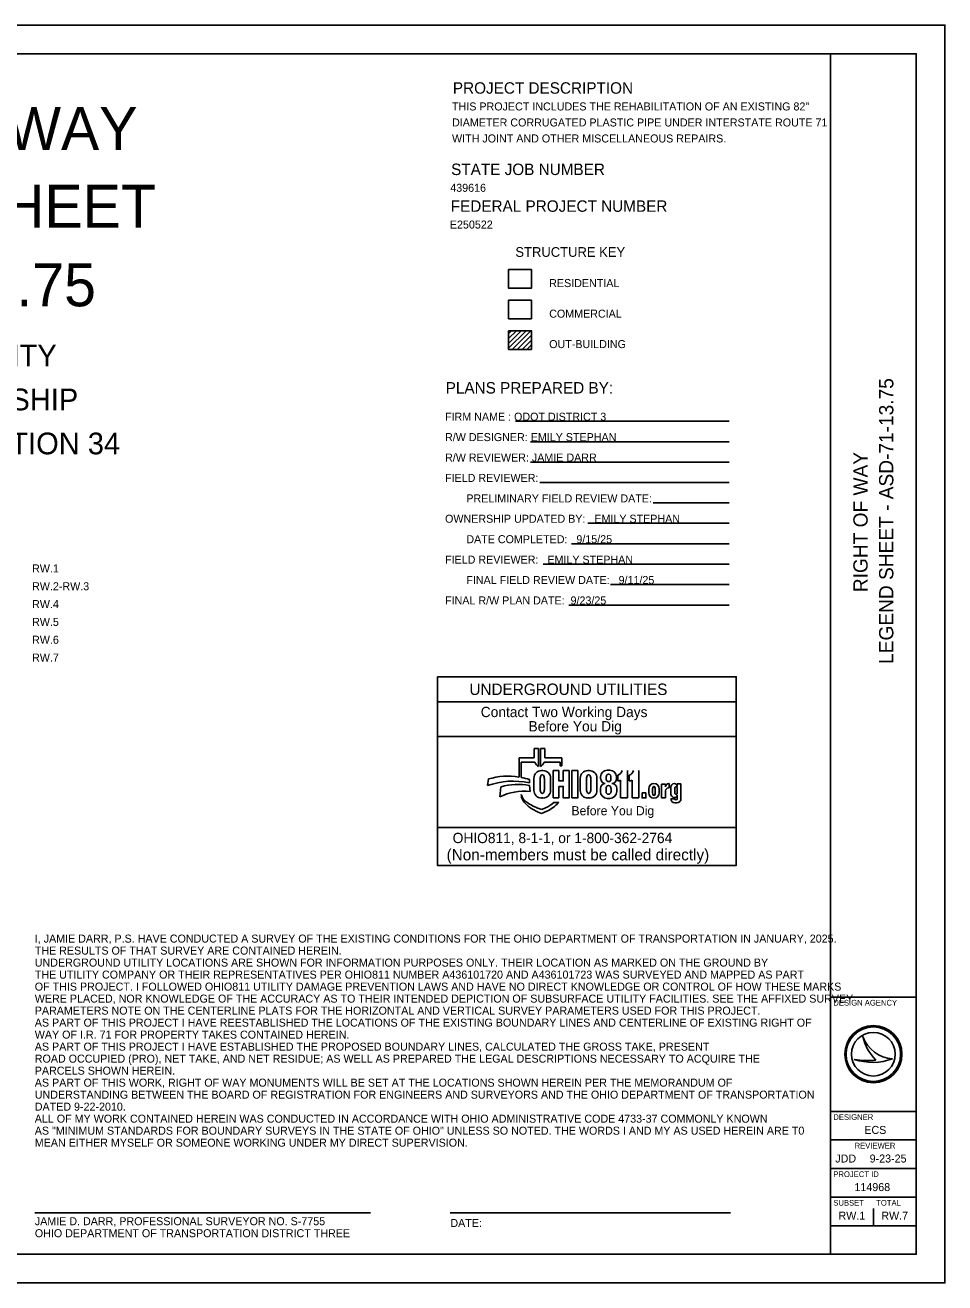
# Model space of a CAD drawing. Extents: x 0 to 34, y 0 to 22.
# Drawn here: x 17.92 to 34, y 0 to 22 of the extents above; entities that cross this region are included whole.
import ezdxf

# ---------------------------------------------------------------- set-up
doc = ezdxf.new("R2010")
doc.units = 0
for name, color, linetype in [('SC_Shading1', 7, 'Continuous'), ('SH_Border', 7, 'Continuous'), ('SH_Cut_Line', 7, 'Continuous'), ('SH_Data', 7, 'Continuous'), ('SH_Text', 7, 'Continuous')]:
    doc.layers.add(name, color=color, linetype=linetype)

msp = doc.modelspace()

# ---------------------------------------------------------------- linework, layer by layer
at = {"layer": 'SC_Shading1'}
msp.add_lwpolyline([(26.372, 16.863), (26.769, 16.863), (26.769, 17.188), (26.372, 17.188)], close=True, dxfattribs=at)
at = {"layer": 'SH_Border'}
for p, q in [((32, 0.5), (32, 21.5)), ((32, 5), (33.5, 5)), ((32, 3), (33.5, 3)), ((32, 2.5), (33.5, 2.5)), ((32, 2), (33.5, 2)), ((32, 1.5), (33.5, 1.5)), ((32, 1), (33.5, 1))]:
    msp.add_line(p, q, dxfattribs=at)
msp.add_lwpolyline([(1.5, 21.5), (33.5, 21.5), (33.5, 0.5), (1.5, 0.5)], close=True, dxfattribs=at)
at = {"layer": 'SH_Cut_Line'}
msp.add_lwpolyline([(0, 0), (34, 0), (34, 22), (0, 22)], close=True, dxfattribs=at)
at = {"layer": 'SH_Data'}
for p, q in [((26.896, 9.349), (26.816, 9.349)), ((26.816, 9.349), (26.816, 9.182)), ((26.896, 9.032), (26.896, 9.349)), ((27.007, 9.349), (26.927, 9.349)), ((26.927, 9.349), (26.927, 9.032)), ((27.007, 9.182), (27.007, 9.349)), ((26.816, 9.182), (26.553, 9.182)), ((26.553, 9.182), (26.553, 8.848)), ((26.59, 8.841), (26.59, 9.105)), ((26.59, 9.105), (26.831, 9.105)), ((26.991, 9.105), (27.27, 9.105)), ((27.304, 9.182), (27.007, 9.182)), ((27.27, 9.105), (27.27, 9.042)), ((27.27, 9.042), (27.304, 9.042)), ((27.304, 9.042), (27.304, 9.182)), ((26.018, 8.814), (26.004, 8.697)), ((26.737, 8.746), (26.737, 8.804)), ((26.814, 8.827), (26.814, 8.615)), ((26.923, 8.632), (26.923, 8.815)), ((26.972, 8.961), (26.948, 8.961)), ((26.997, 8.815), (26.997, 8.632)), ((27.106, 8.615), (27.106, 8.827)), ((27.25, 8.96), (27.149, 8.96)), ((27.149, 8.96), (27.149, 8.482)), ((27.625, 8.827), (27.625, 8.615)), ((27.734, 8.632), (27.734, 8.815)), ((27.783, 8.961), (27.758, 8.961)), ((27.808, 8.815), (27.808, 8.632)), ((27.917, 8.615), (27.917, 8.827)), ((27.981, 8.854), (27.981, 8.817)), ((28.08, 8.8), (28.08, 8.859)), ((28.144, 8.968), (28.095, 8.968)), ((28.161, 8.859), (28.161, 8.8)), ((28.258, 8.817), (28.258, 8.854)), ((28.281, 8.779), (28.281, 8.881)), ((28.448, 8.96), (28.448, 8.482)), ((28.481, 8.779), (28.481, 8.881)), ((28.648, 8.96), (28.648, 8.482)), ((26.238, 8.678), (26.216, 8.499)), ((26.747, 8.595), (26.737, 8.701)), ((27.25, 8.482), (27.25, 8.684)), ((27.976, 8.647), (27.976, 8.596)), ((28.077, 8.587), (28.077, 8.649)), ((28.162, 8.649), (28.162, 8.587)), ((28.264, 8.596), (28.264, 8.647)), ((28.329, 8.482), (28.329, 8.793)), ((28.53, 8.482), (28.53, 8.793)), ((28.822, 8.573), (28.822, 8.64)), ((28.889, 8.571), (28.889, 8.64)), ((28.937, 8.64), (28.937, 8.571)), ((29.004, 8.64), (29.004, 8.573)), ((29.117, 8.725), (29.044, 8.725)), ((29.044, 8.725), (29.044, 8.482)), ((29.117, 8.678), (29.117, 8.725)), ((29.117, 8.482), (29.117, 8.609)), ((29.166, 8.658), (29.178, 8.658)), ((29.178, 8.733), (29.172, 8.733)), ((29.178, 8.658), (29.178, 8.733)), ((29.206, 8.56), (29.206, 8.664)), ((29.278, 8.574), (29.278, 8.65)), ((29.321, 8.68), (29.321, 8.726)), ((29.321, 8.726), (29.386, 8.726)), ((29.321, 8.65), (29.321, 8.574)), ((29.386, 8.726), (29.386, 8.468)), ((26.589, 8.542), (26.594, 8.515)), ((26.948, 8.482), (26.972, 8.482)), ((27.149, 8.482), (27.25, 8.482)), ((27.248, 8.402), (27.162, 8.402)), ((27.245, 8.399), (27.248, 8.402)), ((27.758, 8.482), (27.783, 8.482)), ((28.097, 8.475), (28.143, 8.475)), ((28.448, 8.482), (28.329, 8.482)), ((28.648, 8.482), (28.53, 8.482)), ((29.044, 8.482), (29.117, 8.482)), ((29.206, 8.468), (29.278, 8.468)), ((29.316, 8.398), (29.276, 8.398)), ((29.321, 8.468), (29.321, 8.537)), ((26.954, 8.281), (26.866, 8.311)), ((26.89, 8.235), (26.945, 8.211)), ((26.945, 8.211), (27.04, 8.252)), ((27.016, 8.307), (26.954, 8.281)), ((30.352, 7.303), (25.127, 7.303)), ((32.567, 4.31), (32.567, 4.31)), ((32.75, 4), (32.75, 4)), ((32.417, 3.91), (32.417, 3.91)), ((33.087, 3.919), (33.087, 3.919)), ((32.75, 1), (32.75, 1.3))]:
    msp.add_line(p, q, dxfattribs=at)
for points in [[(25.127, 10.603), (30.352, 10.603), (30.352, 10.163), (25.127, 10.163)], [(25.127, 10.163), (30.352, 10.163), (30.352, 9.558), (25.127, 9.558)], [(25.127, 9.558), (30.352, 9.558), (30.352, 7.963), (25.127, 7.963)], [(28.706, 8.571), (28.772, 8.571), (28.772, 8.482), (28.706, 8.482)], [(25.127, 7.963), (30.352, 7.963), (30.352, 7.303), (25.127, 7.303)]]:
    msp.add_lwpolyline(points, close=True, dxfattribs=at)
for points in [[(27.25, 8.684), (27.326, 8.684), (27.326, 8.482), (27.428, 8.482), (27.428, 8.96), (27.326, 8.96), (27.326, 8.779), (27.25, 8.779), (27.25, 8.96)], [(27.479, 8.482), (27.581, 8.482), (27.581, 8.96), (27.479, 8.96), (27.479, 8.482)], [(28.062, 8.734), (28.062, 8.734)], [(28.178, 8.734), (28.178, 8.734)]]:
    msp.add_lwpolyline(points, dxfattribs=at)
for radius in [0.5, 0.477, 0.477, 0.382]:
    msp.add_circle((32.75, 4), radius, dxfattribs=at)
for centre, radius, start, end in [((26.968, 9.16), 0.147, 201.9296, 240.7469), ((26.855, 9.16), 0.147, 299.2531, 338.0704), ((26.361, 7.639), 1.224, 81.0007, 106.3144), ((26.361, 7.639), 1.224, 72.1402, 79.2074), ((26.948, 8.827), 0.134, 90, 180), ((26.972, 8.827), 0.134, 0, 90), ((27.758, 8.827), 0.134, 90, 180), ((27.783, 8.827), 0.134, 0, 90), ((28.095, 8.854), 0.114, 90, 180), ((28.065, 8.817), 0.0837, 180, 268.1442), ((28.144, 8.854), 0.114, 0, 90), ((28.175, 8.817), 0.0837, 272.2058, 0), ((28.231, 9.003), 0.132, 292.5572, 340.7355), ((28.431, 9.003), 0.132, 292.5572, 340.7355), ((26.455, 7.444), 1.332, 77.8238, 109.8274), ((26.644, 7.651), 0.95, 83.8248, 116.8021), ((26.537, 7.626), 1.094, 79.44, 105.8467), ((26.948, 8.615), 0.134, 180, 270), ((26.972, 8.615), 0.134, 270, 0), ((27.758, 8.615), 0.134, 180, 270), ((27.783, 8.615), 0.134, 270, 0), ((28.062, 8.647), 0.0865, 90, 180), ((28.097, 8.596), 0.121, 180, 270), ((28.143, 8.596), 0.121, 270, 0), ((28.178, 8.647), 0.0865, 0, 90), ((28.269, 8.911), 0.132, 275.1733, 297.0931), ((28.469, 8.911), 0.132, 275.1733, 297.0931), ((28.917, 8.64), 0.0956, 92.5886, 180), ((28.909, 8.64), 0.0956, 0, 87.4114), ((29.172, 8.678), 0.0548, 90, 180), ((29.166, 8.609), 0.0493, 90, 180), ((29.274, 8.664), 0.0686, 92.6865, 180), ((29.268, 8.68), 0.0524, 0, 86.9262), ((26.869, 8.649), 0.3, 201.0457, 232.5314), ((26.805, 8.551), 0.214, 189.6817, 216.0884), ((27.005, 8.697), 0.461, 216.0884, 235.7167), ((27.157, 9.025), 0.773, 232.5314, 241.794), ((26.801, 8.801), 0.538, 293.4582, 312.0712), ((26.801, 8.801), 0.599, 293.4582, 317.8286), ((28.917, 8.573), 0.0956, 180, 267.4114), ((28.909, 8.573), 0.0956, 272.5886, 0), ((29.275, 8.56), 0.0692, 180, 265.7132), ((29.276, 8.468), 0.0699, 180, 270), ((29.274, 8.537), 0.0467, 264.7825, 0), ((29.316, 8.468), 0.0699, 270, 0), ((27.253, 9.061), 0.903, 235.7167, 246.2325), ((27.03, 8.788), 0.504, 241.794, 250.9821), ((33.116, 4.498), 0.58, 198.9257, 198.9319), ((33.347, 4.47), 0.796, 191.6379, 191.6421), ((33.116, 4.498), 0.58, 198.9319, 267.1657), ((33.347, 4.47), 0.796, 191.6421, 226.0947), ((32.739, 4.87), 1.013, 251.4576, 290.0832), ((32.648, 5.154), 1.266, 259.4964, 259.4995), ((32.739, 4.87), 1.013, 251.4527, 251.4576), ((32.648, 5.154), 1.266, 259.4995, 276.6672)]:
    msp.add_arc(centre, radius, start, end, dxfattribs=at)
for centre, major_axis, ratio, start_param, end_param in [((26.96, 8.815), (0, 0.0723), 0.514403, 4.712389, 7.853982), ((27.771, 8.815), (0, 0.0723), 0.514403, 4.712389, 7.853982), ((28.121, 8.859), (0.0404, 0), 0.969373, 0, 3.141593), ((28.121, 8.8), (0.0404, 0), 0.818453, 3.141593, 6.283185), ((26.96, 8.632), (0, 0.0723), 0.514403, 1.570796, 4.712389), ((27.771, 8.632), (0, 0.0723), 0.514403, 1.570796, 4.712389), ((28.119, 8.649), (0, 0.0535), 0.794529, 4.712389, 7.853982), ((28.119, 8.587), (0.0425, 0), 0.959837, 3.141593, 6.283185), ((28.913, 8.64), (0, 0.0434), 0.553236, 4.712389, 7.853982), ((29.299, 8.65), (0, 0.0275), 0.777179, 4.712389, 7.853982), ((28.913, 8.571), (0, 0.046), 0.522014, 1.570796, 4.712389), ((29.299, 8.574), (0, 0.0275), 0.777179, 1.570796, 4.712389), ((29.299, 8.468), (0.0214, 0), 0.959012, 3.141593, 6.283185)]:
    msp.add_ellipse(centre, major_axis=major_axis, ratio=ratio, start_param=start_param, end_param=end_param, dxfattribs=at)
at = {"layer": 'SH_Text'}
for p, q in [((26.372, 16.652), (26.373, 16.653)), ((26.372, 16.602), (26.424, 16.653)), ((26.372, 16.517), (26.508, 16.653)), ((26.372, 16.432), (26.593, 16.653)), ((26.372, 16.348), (26.678, 16.653)), ((26.436, 16.327), (26.762, 16.653)), ((26.521, 16.327), (26.769, 16.575)), ((26.372, 16.332), (26.377, 16.327)), ((26.606, 16.327), (26.769, 16.491)), ((26.691, 16.327), (26.769, 16.406)), ((26.491, 15.071), (30.229, 15.071)), ((26.756, 14.714), (30.229, 14.714)), ((26.756, 14.357), (30.229, 14.357)), ((26.92, 14), (30.229, 14)), ((28.901, 13.642), (30.229, 13.642)), ((27.756, 13.286), (30.229, 13.286)), ((27.47, 12.928), (30.229, 12.928)), ((26.973, 12.571), (30.229, 12.571)), ((28.154, 12.214), (30.229, 12.214)), ((27.425, 11.857), (30.229, 11.857)), ((18.087, 1.226), (23.954, 1.226)), ((25.349, 1.226), (30.249, 1.226))]:
    msp.add_line(p, q, dxfattribs=at)
for points in [[(26.372, 17.724), (26.769, 17.724), (26.769, 17.398), (26.372, 17.398)], [(26.372, 16.653), (26.769, 16.653), (26.769, 16.327), (26.372, 16.327)]]:
    msp.add_lwpolyline(points, close=True, dxfattribs=at)

# ---------------------------------------------------------------- texts
at = {"layer": 'SH_Data'}
for s, height, p in [('RIGHT OF WAY', 0.75, (12.527, 19.816)), ('LEGEND SHEET', 0.75, (12.458, 18.457)), ('ASD-71-13.75', 0.75, (12.8, 17.082)), ('ASHLAND COUNTY', 0.38, (13.782, 16.03)), ('JACKSON TOWNSHIP', 0.38, (13.566, 15.262)), ('SW QUARTER, SECTION 34', 0.38, (12.886, 14.493)), ('RW.1', 0.14, (18.038, 12.427)), ('RW.2-RW.3', 0.14, (18.038, 12.115)), ('RW.4', 0.14, (18.038, 11.803)), ('RW.5', 0.14, (18.038, 11.491)), ('RW.6', 0.14, (18.038, 11.179)), ('RW.7', 0.14, (18.038, 10.867)), ('UNDERGROUND UTILITIES', 0.2, (25.686, 10.283)), ('Contact Two Working Days', 0.18, (25.884, 9.896)), ('Before You Dig', 0.18, (26.719, 9.646)), ('Before You Dig', 0.15972, (27.47, 8.179)), ('OHIO811, 8-1-1, or 1-800-362-2764', 0.18, (25.393, 7.692)), ('(Non-members must be called directly)', 0.2, (25.287, 7.39)), ('DESIGN AGENCY', 0.1, (32.05, 4.85)), ('DESIGNER', 0.1, (32.05, 2.85)), ('ECS', 0.14, (32.592, 2.605)), ('REVIEWER', 0.1, (32.422, 2.35)), ('JDD', 0.14, (32.084, 2.105)), ('9-23-25', 0.14, (32.685, 2.105)), ('PROJECT ID', 0.1, (32.05, 1.85)), ('114968', 0.14, (32.419, 1.605)), ('SUBSET', 0.1, (32.05, 1.35)), ('TOTAL', 0.1, (32.8, 1.35)), ('RW.1', 0.14, (32.14, 1.105)), ('RW.7', 0.14, (32.889, 1.105))]:
    msp.add_text(s, height=height, dxfattribs=at).set_placement(p)
for s, p in [('LEGEND SHEET - ASD-71-13.75', (33.1, 10.827)), ('RIGHT OF WAY', (32.65, 12.082))]:
    msp.add_text(s, height=0.25, rotation=90, dxfattribs=at).set_placement(p)
at = {"layer": 'SH_Text'}
for s, height, p in [('PROJECT DESCRIPTION', 0.2, (25.397, 20.801)), ('THIS PROJECT INCLUDES THE REHABILITATION OF AN EXISTING 82"', 0.14, (25.382, 20.508)), ('DIAMETER CORRUGATED PLASTIC PIPE UNDER INTERSTATE ROUTE 71', 0.14, (25.382, 20.228)), ('WITH JOINT AND OTHER MISCELLANEOUS REPAIRS.', 0.14, (25.382, 19.948)), ('STATE JOB NUMBER', 0.2, (25.366, 19.378)), ('439616', 0.14, (25.351, 19.085)), ('FEDERAL PROJECT NUMBER', 0.2, (25.359, 18.735)), ('E250522', 0.14, (25.344, 18.442)), ('STRUCTURE KEY', 0.17, (26.49, 17.947)), ('RESIDENTIAL', 0.14, (27.081, 17.418)), ('COMMERCIAL', 0.14, (27.081, 16.883)), ('OUT-BUILDING', 0.14, (27.081, 16.351)), ('PLANS PREPARED BY:', 0.2, (25.271, 15.556)), ('FIRM NAME : ODOT DISTRICT 3', 0.14, (25.26, 15.081)), ('R/W DESIGNER: EMILY STEPHAN', 0.14, (25.26, 14.724)), ('R/W REVIEWER: JAMIE DARR', 0.14, (25.26, 14.367)), ('FIELD REVIEWER: ', 0.14, (25.26, 14.01)), ('PRELIMINARY FIELD REVIEW DATE:', 0.14, (25.632, 13.652)), ('OWNERSHIP UPDATED BY:   EMILY STEPHAN', 0.14, (25.26, 13.296)), ('DATE COMPLETED:   9/15/25', 0.14, (25.632, 12.938)), ('FIELD REVIEWER:   EMILY STEPHAN', 0.14, (25.26, 12.581)), ('FINAL FIELD REVIEW DATE:   9/11/25', 0.14, (25.632, 12.224)), ('FINAL R/W PLAN DATE:  9/23/25', 0.14, (25.26, 11.867)), ('I, JAMIE DARR, P.S. HAVE CONDUCTED A SURVEY OF THE EXISTING CONDITIONS FOR THE OHIO DEPARTMENT OF TRANSPORTATION IN JANUARY, 2025.', 0.14, (18.085, 5.952)), ('THE RESULTS OF THAT SURVEY ARE CONTAINED HEREIN.', 0.14, (18.085, 5.742)), ('UNDERGROUND UTILITY LOCATIONS ARE SHOWN FOR INFORMATION PURPOSES ONLY. THEIR LOCATION AS MARKED ON THE GROUND BY', 0.14, (18.085, 5.532)), ('THE UTILITY COMPANY OR THEIR REPRESENTATIVES PER OHIO811 NUMBER A436101720 AND A436101723 WAS SURVEYED AND MAPPED AS PART', 0.14, (18.085, 5.322)), ('OF THIS PROJECT. I FOLLOWED OHIO811 UTILITY DAMAGE PREVENTION LAWS AND HAVE NO DIRECT KNOWLEDGE OR CONTROL OF HOW THESE MARKS', 0.14, (18.085, 5.112)), ('WERE PLACED, NOR KNOWLEDGE OF THE ACCURACY AS TO THEIR INTENDED DEPICTION OF SUBSURFACE UTILITY FACILITIES. SEE THE AFFIXED SURVEY', 0.14, (18.085, 4.902)), ('AS PART OF THIS PROJECT I HAVE REESTABLISHED THE LOCATIONS OF THE EXISTING BOUNDARY LINES AND CENTERLINE OF EXISTING RIGHT OF', 0.14, (18.085, 4.482)), ('PARAMETERS NOTE ON THE CENTERLINE PLATS FOR THE HORIZONTAL AND VERTICAL SURVEY PARAMETERS USED FOR THIS PROJECT.', 0.14, (18.085, 4.692)), ('WAY OF I.R. 71 FOR PROPERTY TAKES CONTAINED HEREIN.', 0.14, (18.085, 4.272)), ('AS PART OF THIS PROJECT I HAVE ESTABLISHED THE PROPOSED BOUNDARY LINES, CALCULATED THE GROSS TAKE, PRESENT', 0.14, (18.085, 4.062)), ('ROAD OCCUPIED (PRO), NET TAKE, AND NET RESIDUE; AS WELL AS PREPARED THE LEGAL DESCRIPTIONS NECESSARY TO ACQUIRE THE', 0.14, (18.085, 3.852)), ('PARCELS SHOWN HEREIN.', 0.14, (18.085, 3.642)), ('AS PART OF THIS WORK, RIGHT OF WAY MONUMENTS WILL BE SET AT THE LOCATIONS SHOWN HEREIN PER THE MEMORANDUM OF', 0.14, (18.085, 3.432)), ('UNDERSTANDING BETWEEN THE BOARD OF REGISTRATION FOR ENGINEERS AND SURVEYORS AND THE OHIO DEPARTMENT OF TRANSPORTATION', 0.14, (18.085, 3.222)), ('DATED 9-22-2010.', 0.14, (18.085, 3.012)), ('ALL OF MY WORK CONTAINED HEREIN WAS CONDUCTED IN ACCORDANCE WITH OHIO ADMINISTRATIVE CODE 4733-37 COMMONLY KNOWN', 0.14, (18.085, 2.802)), ('AS "MINIMUM STANDARDS FOR BOUNDARY SURVEYS IN THE STATE OF OHIO" UNLESS SO NOTED. THE WORDS I AND MY AS USED HEREIN ARE T0', 0.14, (18.085, 2.592)), ('MEAN EITHER MYSELF OR SOMEONE WORKING UNDER MY DIRECT SUPERVISION. ', 0.14, (18.085, 2.382)), ('JAMIE D. DARR, PROFESSIONAL SURVEYOR NO. S-7755', 0.14, (18.086, 1.008)), ('DATE:', 0.14, (25.353, 0.977)), ('OHIO DEPARTMENT OF TRANSPORTATION DISTRICT THREE', 0.14, (18.086, 0.798))]:
    msp.add_text(s, height=height, dxfattribs=at).set_placement(p)

doc.saveas('drawing.dxf')
